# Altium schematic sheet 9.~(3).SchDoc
size 398 x 287 mm
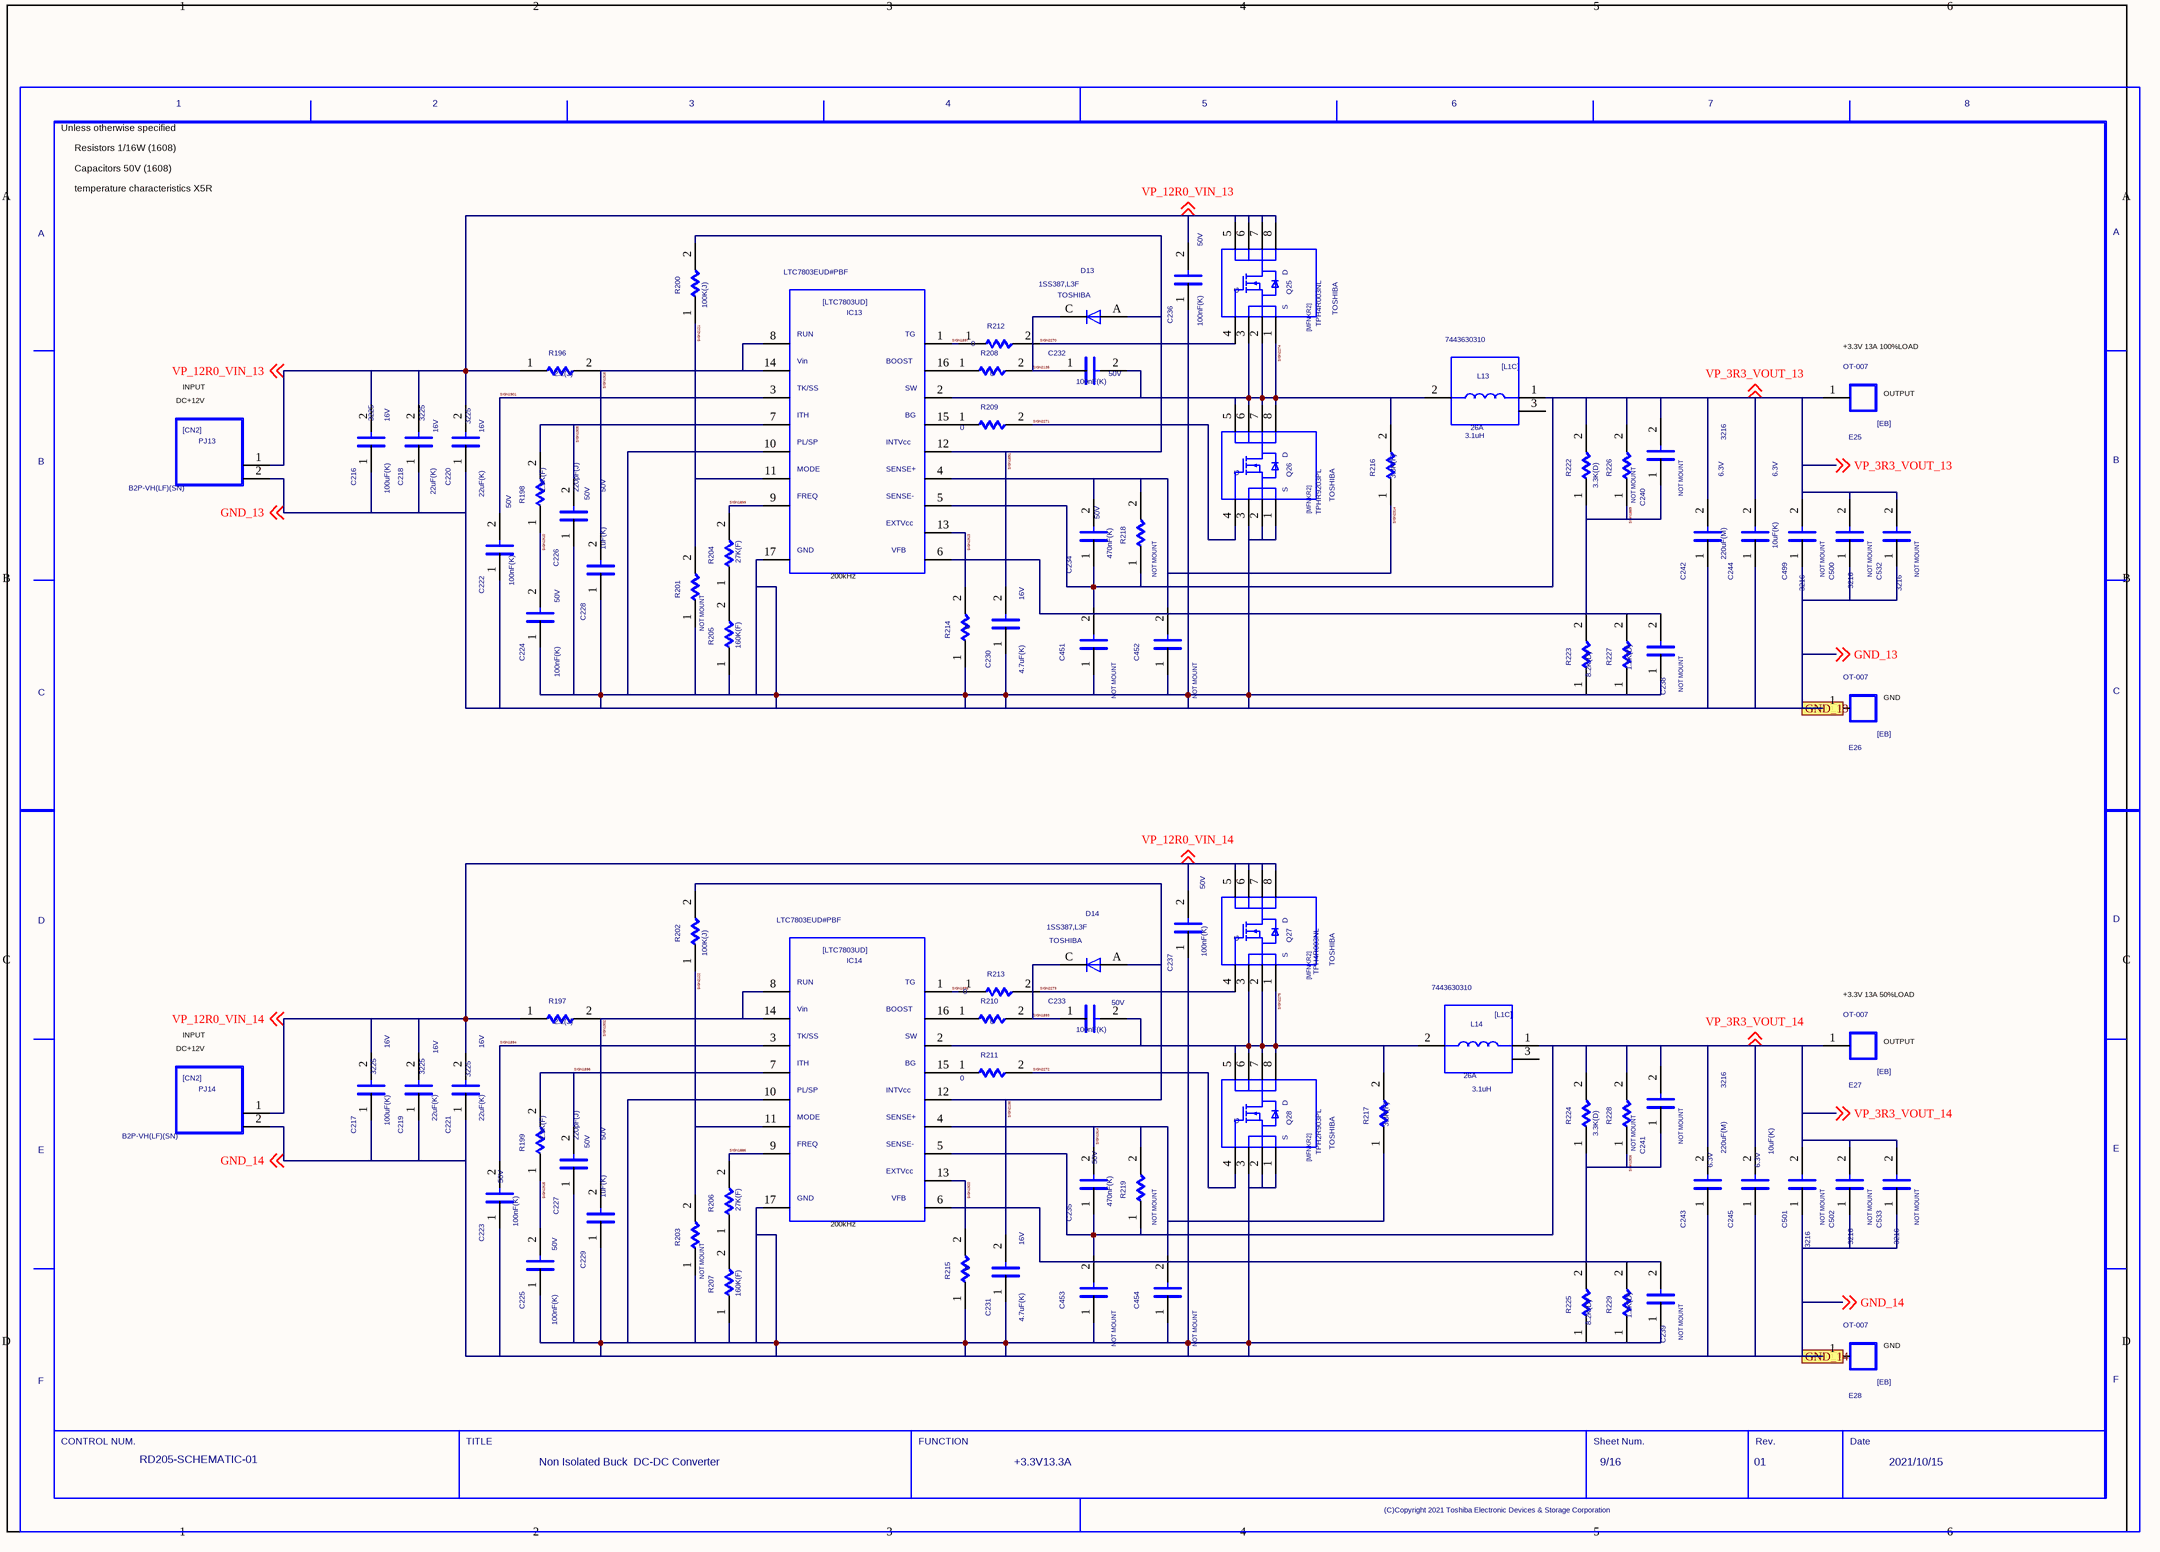
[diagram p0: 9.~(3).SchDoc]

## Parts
C216  SIZECODESMD: 3225  VAL2: 16V  VAL1: 100uF(K)  (hidden comment: C)
C217  SIZECODESMD: 3225  VAL2: 16V  VAL1: 100uF(K)  (hidden comment: C)
C218  SIZECODESMD: 3225  VAL2: 16V  VAL1: 22uF(K)  (hidden comment: C)
C219  SIZECODESMD: 3225  VAL2: 16V  VAL1: 22uF(K)  (hidden comment: C)
C220  SIZECODESMD: 3225  VAL2: 16V  VAL1: 22uF(K)  (hidden comment: C)
C221  SIZECODESMD: 3225  VAL2: 16V  VAL1: 22uF(K)  (hidden comment: C)
C222  VAL2: 50V  VAL1: 100nF(K)  (hidden comment: C)
C223  VAL2: 50V  VAL1: 100nF(K)  (hidden comment: C)
C224  VAL2: 50V  VAL1: 100nF(K)  (hidden comment: C)
C225  VAL2: 50V  VAL1: 100nF(K)  (hidden comment: C)
C226  VAL2: 50V  VAL1: 220pF(J)  (hidden comment: C)
C227  VAL2: 50V  VAL1: 220pF(J)  (hidden comment: C)
C228  VAL2: 50V  VAL1: 1uF(K)  (hidden comment: C)
C229  VAL2: 50V  VAL1: 1uF(K)  (hidden comment: C)
C230  VAL2: 16V  VAL1: 4.7uF(K)  (hidden comment: C)
C231  VAL2: 16V  VAL1: 4.7uF(K)  (hidden comment: C)
C232  VAL2: 50V  VAL1: 100nF(K)  (hidden comment: C)
C233  VAL2: 50V  VAL1: 100nF(K)  (hidden comment: C)
C234  VAL2: 50V  VAL1: 470nF(K)  (hidden comment: C)
C235  VAL2: 50V  VAL1: 470nF(K)  (hidden comment: C)
C236  VAL2: 50V  VAL1: 100nF(K)  (hidden comment: C)
C237  VAL2: 50V  VAL1: 100nF(K)  (hidden comment: C)
C238  NOTMOUNT: NOT MOUNT  (hidden comment: C)
C239  NOTMOUNT: NOT MOUNT  (hidden comment: C)
C240  NOTMOUNT: NOT MOUNT  (hidden comment: C)
C241  NOTMOUNT: NOT MOUNT  (hidden comment: C)
C242  SIZECODESMD: 3216  VAL2: 6.3V  VAL1: 220uF(M)  (hidden comment: C)
C243  SIZECODESMD: 3216  VAL2: 6.3V  VAL1: 220uF(M)  (hidden comment: C)
C244  VAL2: 6.3V  VAL1: 10uF(K)  (hidden comment: C)
C245  VAL2: 6.3V  VAL1: 10uF(K)  (hidden comment: C)
C451  NOTMOUNT: NOT MOUNT  (hidden comment: C)
C452  NOTMOUNT: NOT MOUNT  (hidden comment: C)
C453  NOTMOUNT: NOT MOUNT  (hidden comment: C)
C454  NOTMOUNT: NOT MOUNT  (hidden comment: C)
C499  NOTMOUNT: NOT MOUNT  SIZECODESMD: 3216  (hidden comment: C)
C500  NOTMOUNT: NOT MOUNT  SIZECODESMD: 3216  (hidden comment: C)
C501  NOTMOUNT: NOT MOUNT  SIZECODESMD: 3216  (hidden comment: C)
C502  NOTMOUNT: NOT MOUNT  SIZECODESMD: 3216  (hidden comment: C)
C532  NOTMOUNT: NOT MOUNT  SIZECODESMD: 3216  (hidden comment: C)
C533  NOTMOUNT: NOT MOUNT  SIZECODESMD: 3216  (hidden comment: C)
D13  USERCOMPTEXT3: TOSHIBA  VAL3: 1SS387,L3F  (hidden comment: D)
D14  USERCOMPTEXT3: TOSHIBA  VAL3: 1SS387,L3F  (hidden comment: D)
E25  VAL3: OT-007  (hidden comment: EB)
E26  VAL3: OT-007  (hidden comment: EB)
E27  VAL3: OT-007  (hidden comment: EB)
E28  VAL3: OT-007  (hidden comment: EB)
IC13  VAL3: LTC7803EUD#PBF  (hidden comment: LTC7803UD)
IC14  VAL3: LTC7803EUD#PBF  (hidden comment: LTC7803UD)
L13  VAL3: 7443630310  VAL2: 26A  VAL1: 3.1uH  (hidden comment: L1C)
L14  VAL3: 7443630310  VAL2: 26A  VAL1: 3.1uH  (hidden comment: L1C)
PJ13  VAL3: B2P-VH(LF)(SN)  (hidden comment: CN2)
PJ14  VAL3: B2P-VH(LF)(SN)  (hidden comment: CN2)
Q25  USERCOMPTEXT3: TOSHIBA  VAL3: TPH4R003NL  (hidden comment: MFNKR2)
Q26  USERCOMPTEXT3: TOSHIBA  VAL3: TPHR9203PL  (hidden comment: MFNKR2)
Q27  USERCOMPTEXT3: TOSHIBA  VAL3: TPH4R003NL  (hidden comment: MFNKR2)
Q28  USERCOMPTEXT3: TOSHIBA  VAL3: TPH2R903PL  (hidden comment: MFNKR2)
R196  VAL1: 2.2(J)  (hidden comment: R)
R197  VAL1: 2.2(J)  (hidden comment: R)
R198  VAL1: 1.3K(F)  (hidden comment: R)
R199  VAL1: 1.3K(F)  (hidden comment: R)
R200  VAL1: 100K(J)  (hidden comment: R)
R201  NOTMOUNT: NOT MOUNT  (hidden comment: R)
R202  VAL1: 100K(J)  (hidden comment: R)
R203  NOTMOUNT: NOT MOUNT  (hidden comment: R)
R204  VAL1: 27K(F)  (hidden comment: R)
R205  VAL1: 160K(F)  (hidden comment: R)
R206  VAL1: 27K(F)  (hidden comment: R)
R207  VAL1: 160K(F)  (hidden comment: R)
R208  VAL1: 0  (hidden comment: R)
R209  VAL1: 0  (hidden comment: R)
R210  VAL1: 0  (hidden comment: R)
R211  VAL1: 0  (hidden comment: R)
R212  VAL1: 0  (hidden comment: R)
R213  VAL1: 0  (hidden comment: R)
R214  VAL1: 0  (hidden comment: R)
R215  VAL1: 0  (hidden comment: R)
R216  VAL1: 3.3K(F)  (hidden comment: R)
R217  VAL1: 3.3K(F)  (hidden comment: R)
R218  NOTMOUNT: NOT MOUNT  (hidden comment: R)
R219  NOTMOUNT: NOT MOUNT  (hidden comment: R)
R222  VAL1: 3.3K(D)  (hidden comment: R)
R223  VAL1: 8.2K(D)  (hidden comment: R)
R224  VAL1: 3.3K(D)  (hidden comment: R)
R225  VAL1: 8.2K(D)  (hidden comment: R)
R226  NOTMOUNT: NOT MOUNT  (hidden comment: R)
R227  VAL1: 1.2K(D)  (hidden comment: R)
R228  NOTMOUNT: NOT MOUNT  (hidden comment: R)
R229  VAL1: 1.2K(D)  (hidden comment: R)
U?  DATE: 2021/10/15  SHEETNUMBER: 9/16  TITLE: Non Isolated Buck / DC-DC Converter  REVISION: 01  DRAWINGNUMBER: RD205-SCHEMATIC-01  FUNCTION: +3.3V13.3A  (hidden comment: WAKU_DEF100)

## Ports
GND_13, GND_14

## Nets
GND_13: C216.1 C218.1 C220.1 C222.1 C224.1 C226.1 C228.1 C230.1 C236.1 C238.1 C242.1 C244.1 C451.1 C452.1 C499.1 C500.1 C532.1 E26.1 IC13.10 IC13.17 PJ13.2 Q26.1 Q26.2 Q26.3 R201.1 R205.1 R214.1 R223.1 R227.1 ; off-sheet GND_13, port GND_13
GND_14: C217.1 C219.1 C221.1 C223.1 C225.1 C227.1 C229.1 C231.1 C237.1 C239.1 C243.1 C245.1 C453.1 C454.1 C501.1 C502.1 C533.1 E28.1 IC14.10 IC14.17 PJ14.2 Q28.1 Q28.2 Q28.3 R203.1 R207.1 R215.1 R225.1 R229.1 ; off-sheet GND_14, port GND_14
SIGN1886: IC14.9 R206.2
SIGN1889: C238.2 C240.1 IC13.6 R222.1 R223.2 R226.1 R227.2
SIGN1891: C230.2 D13.A IC13.12 R200.2
SIGN1893: C233.1 D14.C R210.2
SIGN1894: C223.2 IC14.3
SIGN1895: IC14.1 R213.1
SIGN1896: C227.2 IC14.7 R199.2
SIGN1897: IC13.1 R212.1
SIGN1899: IC13.9 R204.2
SIGN1901: C222.2 IC13.3
SIGN1902: C229.2 IC14.8 IC14.14 R197.2
SIGN1906: C239.2 C241.1 IC14.6 R224.1 R225.2 R228.1 R229.2
SIGN1908: C226.2 IC13.7 R198.2
SIGN1910: C224.2 R198.1
SIGN1913: IC13.13 R214.2
SIGN1914: C235.2 C454.2 IC14.4 R217.1 R219.2
SIGN1915: C225.2 R199.1
SIGN1916: C228.2 IC13.8 IC13.14 R196.2
SIGN1920: IC14.13 R215.2
SIGN2121: IC13.11 R200.1 R201.2
SIGN2122: IC14.11 R202.1 R203.2
SIGN2135: C232.1 D13.C R208.2
SIGN2136: C231.2 D14.A IC14.12 R202.2
SIGN2270: Q25.4 R212.2
SIGN2271: Q26.4 R209.2
SIGN2272: Q28.4 R211.2
SIGN2273: Q27.4 R213.2
SIGN2274: C232.2 IC13.2 L13.2 Q25.1 Q25.2 Q25.3 Q26.5 Q26.6 Q26.7 Q26.8 R216.2
SIGN2275: C233.2 IC14.2 L14.2 Q27.1 Q27.2 Q27.3 Q28.5 Q28.6 Q28.7 Q28.8 R217.2
SIGN2314: C234.2 C452.2 IC13.4 R216.1 R218.2
VP_3R3_VOUT_13: C234.1 C240.2 C242.2 C244.2 C451.2 C499.2 C500.2 C532.2 E25.1 IC13.5 L13.1 R218.1 R222.2 R226.2 ; off-sheet VP_3R3_VOUT_13
VP_3R3_VOUT_14: C235.1 C241.2 C243.2 C245.2 C453.2 C501.2 C502.2 C533.2 E27.1 IC14.5 L14.1 R219.1 R224.2 R228.2 ; off-sheet VP_3R3_VOUT_14
VP_12R0_VIN_13: C216.2 C218.2 C220.2 C236.2 PJ13.1 Q25.5 Q25.6 Q25.7 Q25.8 R196.1 ; off-sheet VP_12R0_VIN_13
VP_12R0_VIN_14: C217.2 C219.2 C221.2 C237.2 PJ14.1 Q27.5 Q27.6 Q27.7 Q27.8 R197.1 ; off-sheet VP_12R0_VIN_14
NetIC13_15: IC13.15 R209.1
NetIC13_16: IC13.16 R208.1
NetIC14_15: IC14.15 R211.1
NetIC14_16: IC14.16 R210.1
NetR204_1: R204.1 R205.2
NetR206_1: R206.1 R207.2

Not connected (* = marked no-connect by the designer): L13 3; L14 3

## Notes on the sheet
- Unless otherwise specified
- Resistors 1/16W (1608)
- Capacitors 50V (1608)
- temperature characteristics X5R
- DC+12V
- INPUT
- (near E25) +3.3V 13A 100%LOAD
- (near E25) OUTPUT
- (near IC13) 200kHz
- (near E26) GND
- (near E27) +3.3V 13A 50%LOAD
- (near E27) OUTPUT
- (near IC14) 200kHz
- (near E28) GND

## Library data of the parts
C216 C217 = C: SQ_PART_MODEL: CON_100n; FNPARTSNAMEG: CHIP CERAMIC CAPACITOR (3225); USEINPARTSLIST: YES; OriginalSymbolOrigin: (2540,7620); MFSOLDERINGPROP: .; TEMPCHARACTERI2: B; MFFORMINGDIVP: KC; OUMECLASSIFICATION: セラミックコンデンサ; MFMOUNTSYMBOLP: 90; CDMASTERCADCELG: DC903A; PCODE: P03276001115; FNCLASSCODEG: P03-03; MAXGCOUNT: 1; RATEDVOLTAGE: 250; COMPONENTNAME: G36030160049; OUMEMAKER: KYC 京セラ; MFPACKAGEMETHOP: S; NOMINALCAPACITA: 100n; OUMEMAKERKATAMEI: CF32W5R104K250AT; CAPACITANCETOLE: K
C218-C221 = C: SQ_PART_MODEL: CON_22u; FNPARTSNAMEG: CHIP CERAMIC CAPACITOR (3225); USEINPARTSLIST: YES; OriginalSymbolOrigin: (2540,7620); MFSOLDERINGPROP: .; TEMPCHARACTERI2: B; MFFORMINGDIVP: KC; OUMECLASSIFICATION: セラミックコンデンサ; MFMOUNTSYMBOLP: 80; CDMASTERCADCELG: DC903A; PCODE: P03043035626; FNCLASSCODEG: P03-03; MAXGCOUNT: 1; RATEDVOLTAGE: 6.3; COMPONENTNAME: G36030119054; OUMEMAKER: TYD 太陽誘電; MFPACKAGEMETHOP: S; NOMINALCAPACITA: 22u; OUMEMAKERKATAMEI: JMK325BJ226KM-T; CAPACITANCETOLE: K
C222-C225 C232 C233 C236 C237 = C: SQ_PART_MODEL: CON_100n; FNPARTSNAMEG: CHIP CERAMIC CAPACITOR (1608); USEINPARTSLIST: YES; OriginalSymbolOrigin: (2540,7620); MFSOLDERINGPROP: .; TEMPCHARACTERI2: B; MFFORMINGDIVP: KC; OUMECLASSIFICATION: セラミックコンデンサ; SIZECODESMD: 1608; MFMOUNTSYMBOLP: 80; CDMASTERCADCELG: C8100E; PCODE: P03B000000E4; FNCLASSCODEG: P03-03; MAXGCOUNT: 1; RATEDVOLTAGE: 16; COMPONENTNAME: GDM030000598; OUMEMAKER: MRT 村田製作所; MFPACKAGEMETHOP: S; NOMINALCAPACITA: 100n; OUMEMAKERKATAMEI: GRM188B11C104KA01C; CAPACITANCETOLE: K
C226 = C: SQ_PART_MODEL: CON_220p; FNPARTSNAMEG: CHIP CERAMIC CAPACITOR (1608); USEINPARTSLIST: YES; OriginalSymbolOrigin: (2540,7620); CDMASTERCADCELG: C8100E; MFSOLDERINGPROP: .; TEMPCHARACTERI2: CH; MFFORMINGDIVP: KC; OUMECLASSIFICATION: セラミックコンデンサ; SIZECODESMD: 1608; MFMOUNTSYMBOLP: 80; PCODE: P03039269127; FNCLASSCODEG: P03-03; MAXGCOUNT: 1; RATEDVOLTAGE: 50; COMPONENTNAME: GDM030000578; OUMEMAKER: KYC 京セラ; MFPACKAGEMETHOP: S; NOMINALCAPACITA: 220p; OUMEMAKERKATAMEI: CM105CH221J50AT; CAPACITANCETOLE: J
C227 = C: SQ_PART_MODEL: CON_220p; FNPARTSNAMEG: CHIP CERAMIC CAPACITOR (1608); USEINPARTSLIST: YES; OriginalSymbolOrigin: (2540,7620); MFSOLDERINGPROP: .; TEMPCHARACTERI2: CH; MFFORMINGDIVP: KC; OUMECLASSIFICATION: セラミックコンデンサ; SIZECODESMD: 1608; MFMOUNTSYMBOLP: 80; CDMASTERCADCELG: C8100E; PCODE: P03039269127; FNCLASSCODEG: P03-03; MAXGCOUNT: 1; RATEDVOLTAGE: 50; COMPONENTNAME: GDM030000578; OUMEMAKER: KYC 京セラ; MFPACKAGEMETHOP: S; NOMINALCAPACITA: 220p; OUMEMAKERKATAMEI: CM105CH221J50AT; CAPACITANCETOLE: J
C228 C229 = C: SQ_PART_MODEL: CON_1u; FNPARTSNAMEG: CHIP CERAMIC CAPACITOR (1608); USEINPARTSLIST: YES; OriginalSymbolOrigin: (2540,7620); MFSOLDERINGPROP: .; TEMPCHARACTERI2: B; MFFORMINGDIVP: KC; OUMECLASSIFICATION: セラミックコンデンサ; SIZECODESMD: 1608; MFMOUNTSYMBOLP: 80; CDMASTERCADCELG: C8100E; PCODE: P03039ACE122; FNCLASSCODEG: P03-03; MAXGCOUNT: 1; RATEDVOLTAGE: 6.3; COMPONENTNAME: G36030104159; OUMEMAKER: KYC 京セラ; MFPACKAGEMETHOP: S; NOMINALCAPACITA: 1u; OUMEMAKERKATAMEI: CM105B105K06ATN; CAPACITANCETOLE: K
C230 C231 = C: SQ_PART_MODEL: CON_4.7u; FNPARTSNAMEG: CHIP CERAMIC CAPACITOR (1608); USEINPARTSLIST: YES; OriginalSymbolOrigin: (2540,7620); MFSOLDERINGPROP: .; TEMPCHARACTERI2: B; MFFORMINGDIVP: KC; OUMECLASSIFICATION: セラミックコンデンサ; SIZECODESMD: 1608; MFMOUNTSYMBOLP: 80; CDMASTERCADCELG: C8100E; PCODE: P03B000000MS; FNCLASSCODEG: P03-03; MAXGCOUNT: 1; RATEDVOLTAGE: 4; COMPONENTNAME: GDM030000053; OUMEMAKER: KYC 京セラ; MFPACKAGEMETHOP: S; NOMINALCAPACITA: 4.7u; OUMEMAKERKATAMEI: CM105B475M04AT; CAPACITANCETOLE: M
C234 C235 = C: SQ_PART_MODEL: CON_470n; FNPARTSNAMEG: CHIP CERAMIC CAPACITOR (1608); USEINPARTSLIST: YES; OriginalSymbolOrigin: (2540,7620); MFSOLDERINGPROP: .; TEMPCHARACTERI2: B; MFFORMINGDIVP: KC; OUMECLASSIFICATION: セラミックコンデンサ; SIZECODESMD: 1608; MFMOUNTSYMBOLP: 80; CDMASTERCADCELG: C8100E; PCODE: P03039ABG127; FNCLASSCODEG: P03-03; MAXGCOUNT: 1; RATEDVOLTAGE: 10; COMPONENTNAME: GDM030001129; OUMEMAKER: KYC 京セラ; MFPACKAGEMETHOP: S; NOMINALCAPACITA: 470n; OUMEMAKERKATAMEI: CM105B474K10AT; CAPACITANCETOLE: K
C238-C241 = C: SQ_PART_MODEL: CON_100p; FNPARTSNAMEG: CHIP CERAMIC CAPACITOR (1608); USEINPARTSLIST: YES; OriginalSymbolOrigin: (2540,7620); TOLERANCE: J; ASIMVALUE: 100P; MFSOLDERINGPROP: .; TEMPCHARACTERI2: CH; MFFORMINGDIVP: KC; OUMECLASSIFICATION: セラミックコンデンサ; SIZECODESMD: 1608; MFMOUNTSYMBOLP: 80; CDMASTERCADCELG: C8100E; PCODE: P03039177125; FNCLASSCODEG: P03-03; MAXGCOUNT: 1; RATEDVOLTAGE: 50; COMPONENTNAME: G36030011365; OUMEMAKER: KYC 京セラ; MFPACKAGEMETHOP: S; OUMEMAKERKATAMEI: CM105CH101J50AT; VAL2: 50V; VAL1: 100pF(J)
C242 C243 = C: SQ_PART_MODEL: CON_22u; FNPARTSNAMEG: CHIP CERAMIC CAPACITOR (3216); USEINPARTSLIST: YES; OriginalSymbolOrigin: (2540,7620); MFSOLDERINGPROP: .; TEMPCHARACTERI2: B; MFFORMINGDIVP: KC; OUMECLASSIFICATION: セラミックコンデンサ; MFMOUNTSYMBOLP: 80; CDMASTERCADCELG: DC901A; PCODE: P03B0000004V; FNCLASSCODEG: P03-03; MAXGCOUNT: 1; RATEDVOLTAGE: 6.3; COMPONENTNAME: GDM030000020; OUMEMAKER: KYC 京セラ; MFPACKAGEMETHOP: S; NOMINALCAPACITA: 22u; OUMEMAKERKATAMEI: CM316B226M06AT; CAPACITANCETOLE: M
C244 C245 = C: SQ_PART_MODEL: CON_1u; FNPARTSNAMEG: CHIP CERAMIC CAPACITOR (1608); PARTCOMMENT: 代表セル<KC0008> がフットプリントに登録されていません。; USEINPARTSLIST: YES; OriginalSymbolOrigin: (2540,7620); MFSOLDERINGPROP: .; TEMPCHARACTERI2: B; MFFORMINGDIVP: KC; OUMECLASSIFICATION: セラミックコンデンサ; SIZECODESMD: 1608; MFMOUNTSYMBOLP: 80; CDMASTERCADCELG: KC0008; PCODE: P03B000000ZQ; FNCLASSCODEG: P03-03; MAXGCOUNT: 1; RATEDVOLTAGE: 6.3; COMPONENTNAME: GDM030000202; OUMEMAKER: MRT 村田製作所; MFPACKAGEMETHOP: S; NOMINALCAPACITA: 1u; OUMEMAKERKATAMEI: GRM185B10J105KE21D; CAPACITANCETOLE: K
C451-C454 = C: SQ_PART_MODEL: CON_220n; FNPARTSNAMEG: CHIP CERAMIC CAPACITOR (1608); PARTCOMMENT: 代表セル<KC0008> がフットプリントに登録されていません。; USEINPARTSLIST: YES; OriginalSymbolOrigin: (2540,7620); MFSOLDERINGPROP: .; TEMPCHARACTERI2: B; MFFORMINGDIVP: KC; OUMECLASSIFICATION: セラミックコンデンサ; SIZECODESMD: 1608; MFMOUNTSYMBOLP: 80; CDMASTERCADCELG: KC0008; PCODE: P03B000001L3; FNCLASSCODEG: P03-03; MAXGCOUNT: 1; RATEDVOLTAGE: 16; COMPONENTNAME: GDM030001129; OUMEMAKER: MRT 村田製作所; MFPACKAGEMETHOP: S; NOMINALCAPACITA: 220n; OUMEMAKERKATAMEI: GRM188B11C224KA01D; VAL2: 16V; VAL1: 220nF(K); CAPACITANCETOLE: K
C499-C502 C532 C533 = C: SQ_PART_MODEL: CON_22u; FNPARTSNAMEG: CHIP CERAMIC CAPACITOR (3216); USEINPARTSLIST: YES; OriginalSymbolOrigin: (2540,7620); MFSOLDERINGPROP: .; TEMPCHARACTERI2: B; MFFORMINGDIVP: KC; OUMECLASSIFICATION: セラミックコンデンサ; MFMOUNTSYMBOLP: 80; CDMASTERCADCELG: DC901A; PCODE: P03B0000004V; FNCLASSCODEG: P03-03; MAXGCOUNT: 1; RATEDVOLTAGE: 6.3; COMPONENTNAME: GDM030000020; OUMEMAKER: KYC 京セラ; MFPACKAGEMETHOP: S; NOMINALCAPACITA: 22u; OUMEMAKERKATAMEI: CM316B226M06AT; VAL2: 6.3V; VAL1: 22uF(M); CAPACITANCETOLE: M
D13 D14 = D: FNPARTSNAMEG: DIODE; USEINPARTSLIST: YES; PARTNAME: GDM420000143; SAVEAREA0: -565,-171,12979,8058; SAVECOUNT: 1; TIME: 14:49:55; UPDATEUSER: 19870035; UPDATETIME: 14:20:16; OriginalSymbolOrigin: (5080,5080); FORWARDVOLTAGEM: 0; MAXREVERSEVOLTA: 80; COMPONENTNAME: GDM420000143_package; MFSOLDERINGPROP: .; OUMEMAKER: TSB 東芝（ＹＰＳＳ）; QUADMODEL: dummymodel; MFPACKAGEMETHOP: S; MFFORMINGDIVP: MM; MOUNTINGFORMSMD: SMD; OUMECLASSIFICATION: 小信号ダイオード; OUMEMAKERKATAMEI: 1SS387(TPH3,F); CDMASTERCADCELG: D8101D; PCODE: P42B0000008E; FNCLASSCODEG: P42-01
E25-E28 = EB: FNPARTSNAMEG: TERMINAL; USEINPARTSLIST: YES; PARTNAME: 5P9L1232P001; OUMEPARTTYPE: TB; OriginalSymbolOrigin: (2540,12700); COMPONENTNAME: 5P9L1232P001_package; MAXGCOUNT: 1; MFSOLDERINGPROP: .; OUMEMAKER: オサダ; QUADMODEL: dummymodel; MFPACKAGEMETHOP: I; MFFORMINGDIVP: OD; OUMECLASSIFICATION: 端子台、端子板; CDMASTERCADCELG: DE0009; KIND: PBS; PCODE: P29045001117; TERMINALSTYLE: SC; FNCLASSCODEG: P29-01
IC13 IC14 = LTC7803UD: USEINPARTSLIST: YES; SAVECOUNT: 29; SAVEAREA0: -53177,0,89020,58420; TIME: 16:14:14; UPDATEUSER: q91866sr; UPDATETIME: 13:15:36; OriginalSymbolOrigin: (5080,55880); MAXGCOUNT: 1; COMPONENTNAME: LTC7803UD_LTC7803UD; OUMEMAKER: ANALOG DEVICES
L13 L14 = L1C: USEINPARTSLIST: YES; PARTNAME: 7443630140; SAVECOUNT: 6; SAVEAREA0: -5636,-341,27978,18652; OriginalSymbolOrigin: (5080,15240); COMPONENTNAME: L1C_L1C; MAXGCOUNT: 1; OUMEMAKER: WURTH
PJ13 PJ14 = CN2: FNPARTSNAMEG: 3.96PITCH NYLON CONNECTOR; USEINPARTSLIST: YES; PARTNAME: G36220114012; OUMEPARTTYPE: CN; OriginalSymbolOrigin: (2540,15240); MAXGCOUNT: 1; RATEDCURRENT: 7; COMPONENTNAME: G36220114012_package; MFSOLDERINGPROP: .; OUMEMAKER: JST 日本圧着端子製造; NUMBEROFCONTACT: 2; QUADMODEL: dummymodel; MFPACKAGEMETHOP: I; MFFORMINGDIVP: CU; CONTACTPITCH: 3.96m; OUMEMAKERKATAMEI: B2P-VH; CDMASTERCADCELG: DPJ514; PCODE: P22346001114; TERMINALSTYLE: PW; FNCLASSCODEG: P22-10
Q25-Q28 = MFNKR2: USEINPARTSLIST: YES; PARTNAME: TPH6R003NL; SAVEAREA0: -9199,-39,32138,22820; TIME: 18:57:44; UPDATEUSER: q91866sr; UPDATETIME: 12:36:02; SAVECOUNT: 10; OriginalSymbolOrigin: (5080,20320); MAXGCOUNT: 1; COMPONENTNAME: MFNKR2_MFNKR2
R196 R197 = R: SQ_PART_MODEL: RES_2.2; FNPARTSNAMEG: CHIP RESISTOR (1608); USEINPARTSLIST: YES; OriginalSymbolOrigin: (5080,5080); TOLERANCE: J; ASIMVALUE: 2.2; MAXGCOUNT: 1; COMPONENTNAME: G36010011507; MFSOLDERINGPROP: .; OUMEMAKER: NAE 松下電子部品; MFPACKAGEMETHOP: S; MFFORMINGDIVP: KC; MOUNTINGFORMSMD: SMD; OUMECLASSIFICATION: 表面実装用固定抵抗器; MFMOUNTSYMBOLP: 80; POWERRATING: 63m; OUMEMAKERKATAMEI: ERJ3GEYJ2R2V; NUMBEROFELEMENT: 0; VAL2: 62.5mW; CDMASTERCADCELG: DR802R; PCODE: P01042157622; FNCLASSCODEG: P01-08
R198 R199 = R: SQ_PART_MODEL: RES_1.3K; FNPARTSNAMEG: CHIP RESISTOR (1608); USEINPARTSLIST: YES; OriginalSymbolOrigin: (5080,5080); TOLERANCE: F; ASIMVALUE: 1.3K; MAXGCOUNT: 1; COMPONENTNAME: G36010104049; MFSOLDERINGPROP: .; OUMEMAKER: HDK 北陸電気工業; MFPACKAGEMETHOP: S; MFFORMINGDIVP: KC; MOUNTINGFORMSMD: SMD; OUMECLASSIFICATION: 表面実装用固定抵抗器; MFMOUNTSYMBOLP: 80; POWERRATING: 63m; OUMEMAKERKATAMEI: CR1/16 132FV; NUMBEROFELEMENT: 0; VAL2: 62.5mW; CDMASTERCADCELG: DR802R; PCODE: P01042017223; FNCLASSCODEG: P01-08
R200 R202 = R: SQ_PART_MODEL: RES_100K; FNPARTSNAMEG: CHIP RESISTOR (1608); USEINPARTSLIST: YES; OriginalSymbolOrigin: (5080,5080); TOLERANCE: J; ASIMVALUE: 100K; MFSOLDERINGPROP: .; MFPACKAGEMETHOP: S; MFFORMINGDIVP: KC; MOUNTINGFORMSMD: SMD; MFMOUNTSYMBOLP: 80; NUMBEROFELEMENT: 0; PCODE: P01042047220; MAXGCOUNT: 1; COMPONENTNAME: G36010011057; OUMEMAKER: HDK 北陸電気工業; OUMECLASSIFICATION: 表面実装用固定抵抗器; POWERRATING: 63m; OUMEMAKERKATAMEI: CR1/16 104JV; VAL2: 62.5mW; CDMASTERCADCELG: DR802R; FNCLASSCODEG: P01-08
R201 R203 = R: SQ_PART_MODEL: RES_10; FNPARTSNAMEG: CHIP RESISTOR (1608); USEINPARTSLIST: YES; OriginalSymbolOrigin: (5080,5080); TOLERANCE: F; ASIMVALUE: 10; MFSOLDERINGPROP: .; MFPACKAGEMETHOP: S; MFFORMINGDIVP: KC; MOUNTINGFORMSMD: SMD; MFMOUNTSYMBOLP: 80; NUMBEROFELEMENT: 0; PCODE: P01042036620; MAXGCOUNT: 1; COMPONENTNAME: G36010104063; OUMEMAKER: NAE 松下電子部品; OUMECLASSIFICATION: 表面実装用固定抵抗器; POWERRATING: 63m; OUMEMAKERKATAMEI: ERJ3GEYF100V; VAL2: 62.5mW; VAL1: 10(F); CDMASTERCADCELG: DR802R; FNCLASSCODEG: P01-08
R204 R206 = R: SQ_PART_MODEL: RES_27K; FNPARTSNAMEG: CHIP RESISTOR (1608); USEINPARTSLIST: YES; OriginalSymbolOrigin: (5080,5080); MAXGCOUNT: 1; TOLERANCE: F; COMPONENTNAME: G36010027195; MFSOLDERINGPROP: .; OUMEMAKER: NAE 松下電子部品; MFPACKAGEMETHOP: S; MFFORMINGDIVP: KC; MOUNTINGFORMSMD: SMD; OUMECLASSIFICATION: 表面実装用固定抵抗器; ASIMVALUE: 27K; MFMOUNTSYMBOLP: 80; POWERRATING: 63m; OUMEMAKERKATAMEI: ERJ3GEYF273V; NUMBEROFELEMENT: 0; VAL2: 62.5mW; CDMASTERCADCELG: DR802R; PCODE: P01042508622; FNCLASSCODEG: P01-08
R205 R207 = R: SQ_PART_MODEL: RES_160K; FNPARTSNAMEG: CHIP RESISTOR (1608); USEINPARTSLIST: YES; OriginalSymbolOrigin: (5080,5080); MAXGCOUNT: 1; COMPONENTNAME: G51011061108; MFSOLDERINGPROP: .; OUMEMAKER: HDK 北陸電気工業; MFPACKAGEMETHOP: S; MFFORMINGDIVP: KC; MOUNTINGFORMSMD: SMD; OUMECLASSIFICATION: 表面実装用固定抵抗器; RESISTANCETOLER: F; MFMOUNTSYMBOLP: 80; POWERRATING: 63m; OUMEMAKERKATAMEI: CR1/16 164FV; NOMINALRESISTAN: 160K; NUMBEROFELEMENT: 0; VAL2: 62.5mW; CDMASTERCADCELG: DR802R; PCODE: P01042125225; FNCLASSCODEG: P01-08
R208 R210 R214 R215 = R: SQ_PART_MODEL: RES_10; FNPARTSNAMEG: CHIP RESISTOR (1608); USEINPARTSLIST: YES; OriginalSymbolOrigin: (5080,5080); TOLERANCE: F; ASIMVALUE: 10; MFSOLDERINGPROP: .; MFPACKAGEMETHOP: S; MFFORMINGDIVP: KC; MOUNTINGFORMSMD: SMD; MFMOUNTSYMBOLP: 80; PCODE: P01042036620; MAXGCOUNT: 1; COMPONENTNAME: G36010104063; OUMEMAKER: NAE 松下電子部品; OUMECLASSIFICATION: 表面実装用固定抵抗器; POWERRATING: 63m; OUMEMAKERKATAMEI: ERJ3GEYF100V; VAL2: 62.5mW; CDMASTERCADCELG: DR802R; FNCLASSCODEG: P01-08
R209 R211-R213 = R: SQ_PART_MODEL: RES_10; FNPARTSNAMEG: CHIP RESISTOR (2012); USEINPARTSLIST: YES; OriginalSymbolOrigin: (5080,5080); MAXGCOUNT: 1; TOLERANCE: F; COMPONENTNAME: 5P9L1083P100; MFSOLDERINGPROP: .; OUMEMAKER: 北陸電気工業; MFPACKAGEMETHOP: S; MFFORMINGDIVP: KC; MOUNTINGFORMSMD: SMD; OUMECLASSIFICATION: 表面実装用固定抵抗器; ASIMVALUE: 10; MFMOUNTSYMBOLP: 90; POWERRATING: 100m; OUMEMAKERKATAMEI: CR1/10 100FV Pb(F); VAL2: 125mW; CDMASTERCADCELG: DR910A; PCODE: P01043091222; FNCLASSCODEG: P01-08
R216 R217 = R: SQ_PART_MODEL: RES_3.3K; FNPARTSNAMEG: CHIP RESISTOR (1608); USEINPARTSLIST: YES; OriginalSymbolOrigin: (5080,5080); TOLERANCE: F; ASIMVALUE: 3.3K; MAXGCOUNT: 1; COMPONENTNAME: G5101105R107; MFSOLDERINGPROP: .; OUMEMAKER: ROH ロー・; MFPACKAGEMETHOP: S; MFFORMINGDIVP: KC; MOUNTINGFORMSMD: SMD; OUMECLASSIFICATION: 表面実装用固定抵抗器; MFMOUNTSYMBOLP: 80; POWERRATING: 63m; OUMEMAKERKATAMEI: MCR03EZPFX3301; NUMBEROFELEMENT: 0; VAL2: 62.5mW; CDMASTERCADCELG: DR802R; PCODE: P01042250729; FNCLASSCODEG: P01-08
R218 R219 = R: SQ_PART_MODEL: RES_68K; FNPARTSNAMEG: CHIP RESISTOR (1608); USEINPARTSLIST: YES; OriginalSymbolOrigin: (5080,5080); TOLERANCE: F; ASIMVALUE: 68K; MAXGCOUNT: 1; COMPONENTNAME: G36010027126; MFSOLDERINGPROP: .; OUMEMAKER: HDK 北陸電気工業; MFPACKAGEMETHOP: S; MFFORMINGDIVP: KC; MOUNTINGFORMSMD: SMD; OUMECLASSIFICATION: 表面実装用固定抵抗器; MFMOUNTSYMBOLP: 80; POWERRATING: 63m; OUMEMAKERKATAMEI: CR1/16 683FV; NUMBEROFELEMENT: 0; VAL2: 62.5mW; VAL1: 68K(F); CDMASTERCADCELG: DR802R; PCODE: P01042456220; FNCLASSCODEG: P01-08
R222 R224 = R: SQ_PART_MODEL: RES_3.3K; FNPARTSNAMEG: CHIP RESISTOR (1608); USEINPARTSLIST: YES; OriginalSymbolOrigin: (5080,5080); MAXGCOUNT: 1; COMPONENTNAME: G36010014485; MFSOLDERINGPROP: .; OUMEMAKER: SSM 進工業; MFPACKAGEMETHOP: S; MFFORMINGDIVP: KC; MOUNTINGFORMSMD: SMD; OUMECLASSIFICATION: 表面実装用固定抵抗器; RESISTANCETOLER: D; MFMOUNTSYMBOLP: 80; POWERRATING: 63m; OUMEMAKERKATAMEI: RR0816P-332-D; NOMINALRESISTAN: 3.3K; NUMBEROFELEMENT: 0; VAL2: 62.5mW; CDMASTERCADCELG: DR802R; PCODE: P01042249822; FNCLASSCODEG: P01-08
R223 R225 = R: ICX_PART_MODEL: RES_8.2K; FNPARTSNAMEG: CHIP RESISTOR (1608); OriginalSymbolOrigin: (5080,5080); FNCLASSCODEG: P01-08; PCODE: P01117051114; CDMASTERCADCELG: DR802R; USEWITHSCHEMA: YES; VAL2: 62.5mW; NUMBEROFELEMENT: 0; NOMINALRESISTAN: 8.2K; OUMEMAKERKATAMEI: RK73G1JTD822D; POWERRATING: 63m; MFMOUNTSYMBOLP: 80; RESISTANCETOLER: D; FUNCTION: G36010129479; OUMECLASSIFICATION: 表面実装用固定抵抗器; MOUNTINGFORMSMD: SMD; MFFORMINGDIVP: KC; MFPACKAGEMETHOP: S; OUMEMAKER: KOA ＫＯＡ; MFSOLDERINGPROP: .; MAXGCOUNT: 1
R226 R228 = R: SQ_PART_MODEL: RES_3.3K; FNPARTSNAMEG: CHIP RESISTOR (1608); USEINPARTSLIST: YES; OriginalSymbolOrigin: (5080,5080); TOLERANCE: F; ASIMVALUE: 3.3K; MAXGCOUNT: 1; COMPONENTNAME: G36010027027; MFSOLDERINGPROP: .; OUMEMAKER: ROH ロー・; MFPACKAGEMETHOP: S; MFFORMINGDIVP: KC; MOUNTINGFORMSMD: SMD; OUMECLASSIFICATION: 表面実装用固定抵抗器; MFMOUNTSYMBOLP: 80; POWERRATING: 63m; OUMEMAKERKATAMEI: MCR03EZPFX3301; NUMBEROFELEMENT: 0; VAL2: 62.5mW; VAL1: 3.3K(F); CDMASTERCADCELG: DR802R; PCODE: P01042250729; FNCLASSCODEG: P01-08
R227 R229 = R: ICX_PART_MODEL: RES_1.2K; FNPARTSNAMEG: CHIP RESISTOR (1608); OriginalSymbolOrigin: (5080,5080); FNCLASSCODEG: P01-08; PCODE: P01117031116; CDMASTERCADCELG: DR802R; USEWITHSCHEMA: YES; VAL2: 62.5mW; NUMBEROFELEMENT: 0; NOMINALRESISTAN: 1.2K; OUMEMAKERKATAMEI: RK73G1JTD122D; POWERRATING: 63m; MFMOUNTSYMBOLP: 80; RESISTANCETOLER: D; FUNCTION: G36010129271; OUMECLASSIFICATION: 表面実装用固定抵抗器; MOUNTINGFORMSMD: SMD; MFFORMINGDIVP: KC; MFPACKAGEMETHOP: S; OUMEMAKER: KOA ＫＯＡ; MFSOLDERINGPROP: .; MAXGCOUNT: 1
U? = WAKU_DEF100: PLOTTIME: HH:MM; SAVEAREA0: 330961,54,387907,31546; TIME: 19:23:07; UPDATEUSER: t5459927; UPDATETIME: 15:33:41; SAVECOUNT: 6; OriginalSymbolOrigin: (10160,284480); DESIGNED: ***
